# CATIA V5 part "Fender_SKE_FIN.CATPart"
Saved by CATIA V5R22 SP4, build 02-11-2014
Part number: Fender
Bounding box of the stored display mesh (mm): x -800 to 0, y 0 to 122.295, z 0 to 580
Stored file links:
  C:\DATA\Car_ASSY\教育モデル\2_SKE\Fender_SKE_FIN.CATPart
  C:\DATA\Car_ASSY\教育モデル\3_SOL\Car_Fender.CATPart
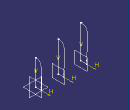
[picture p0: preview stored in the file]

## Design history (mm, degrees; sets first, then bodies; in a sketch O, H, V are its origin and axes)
Set1
  Plane1: type Offset, RefPlane yz-plane, Offset 400, reversed
  Plane2: type Offset, RefPlane Plane1, Offset 400, reversed
Body1 (main body)
Body2
  Sketch1 on yz-plane, origin (0, 0, 0), H (0, 1, 0), V (0, 0, 1)
    point P4 (100, 50)
    point P5 (10, 450)
    spline S1 through (10, 450) (100, 50)
    line L1 (0, 450) -> (10, 450)
    line L2 (0, 0) -> (0, 450)
    line L3 (100, 0) -> (0, 0)
    line L4 (100, 50) -> (100, 0)
    point P6 (100, 50)
    point P7 (10, 450)
    distance P4 L3 = 50
    distance P5 L2 = 10
    distance L4 L2 = 100
    distance L1 H = 450
    coincidence: L2 V, H L3, P4 P6, P7 P5
  Sketch2 on Plane1, origin (-400, 0, 0), H (0, 1, 0), V (0, 0, 1)
    point P4 (100, 50)
    point P5 (10, 530)
    spline S1 through (10, 530) (100, 50)
    line L1 (0, 530) -> (10, 530)
    line L2 (0, 0) -> (0, 530)
    line L3 (100, 0) -> (0, 0)
    line L4 (100, 50) -> (100, 0)
    point P6 (100, 50)
    point P7 (10, 530)
    distance P4 L3 = 50
    distance P5 L2 = 10
    distance L4 L2 = 100
    distance L1 H = 530
    coincidence: L2 V, H L3, P4 P6, P7 P5
  Sketch3 on Plane2, origin (-800, 0, 0), H (0, 1, 0), V (0, 0, 1)
    point P4 (100, 50)
    point P5 (10, 580)
    spline S1 through (10, 580) (100, 50)
    line L1 (0, 580) -> (10, 580)
    line L2 (0, 0) -> (0, 580)
    line L3 (100, 0) -> (0, 0)
    line L4 (100, 50) -> (100, 0)
    point P6 (100, 50)
    point P7 (10, 580)
    distance P4 L3 = 50
    distance P5 L2 = 10
    distance L4 L2 = 100
    distance L1 H = 580
    coincidence: L2 V, H L3, P4 P6, P7 P5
